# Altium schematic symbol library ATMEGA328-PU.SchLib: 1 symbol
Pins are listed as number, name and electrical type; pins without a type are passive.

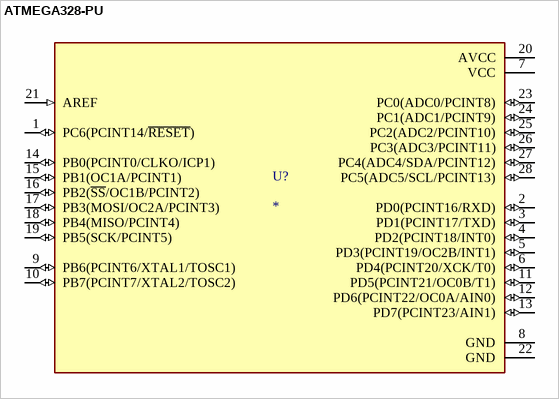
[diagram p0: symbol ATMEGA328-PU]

## ATMEGA328-PU
designator U?
AVR AVRÂ® ATmega Microcontroller IC 8-Bit 20MHz 32KB (16K x 16) FLASH 28-PDIP; MP: ATMEGA328-PU; MF: Microchip
footprint DIP787W46P254L3467H508Q28
pins: 1 PC6(PCINT14/~{RESET}) (io), 2 PD0(PCINT16/RXD) (io), 3 PD1(PCINT17/TXD) (io), 4 PD2(PCINT18/INT0) (io), 5 PD3(PCINT19/OC2B/INT1) (io), 6 PD4(PCINT20/XCK/T0) (io), 7 VCC (power), 8 GND (power), 9 PB6(PCINT6/XTAL1/TOSC1) (io), 10 PB7(PCINT7/XTAL2/TOSC2) (io), 11 PD5(PCINT21/OC0B/T1) (io), 12 PD6(PCINT22/OC0A/AIN0) (io), 13 PD7(PCINT23/AIN1) (io), 14 PB0(PCINT0/CLKO/ICP1) (io), 15 PB1(OC1A/PCINT1) (io), 16 PB2(~{SS}/OC1B/PCINT2) (io), 17 PB3(MOSI/OC2A/PCINT3) (io), 18 PB4(MISO/PCINT4) (io), 19 PB5(SCK/PCINT5) (io), 20 AVCC (power), 21 AREF (in), 22 GND (power), 23 PC0(ADC0/PCINT8) (io), 24 PC1(ADC1/PCINT9) (io), 25 PC2(ADC2/PCINT10) (io), 26 PC3(ADC3/PCINT11) (io), 27 PC4(ADC4/SDA/PCINT12) (io), 28 PC5(ADC5/SCL/PCINT13) (io)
